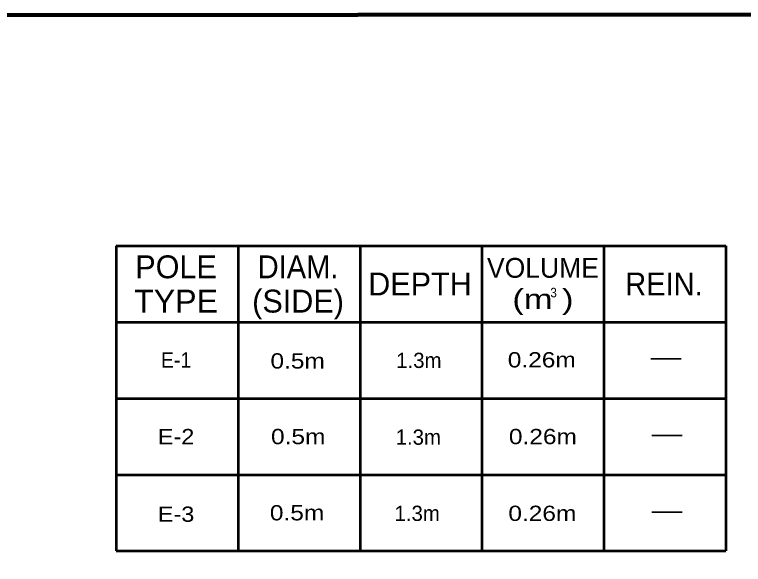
# Model space of a CAD drawing. Extents: x -761 to 95, y 34 to 578.
# Drawn here: x -361.7 to -247, y 485.5 to 571.9 of the extents above; entities that cross this region are included whole.
import ezdxf
from ezdxf.enums import TextEntityAlignment as Align

# ---------------------------------------------------------------- set-up
doc = ezdxf.new("R2010")
doc.units = 0
doc.header["$LTSCALE"] = 0.96
doc.layers.add('1', color=7, linetype='Continuous', lineweight=53)

msp = doc.modelspace()

# ---------------------------------------------------------------- linework, layer by layer
at = {"layer": '1'}
for p, q in [((-326.5549, 535.5653), (-326.5549, 487.5653)), ((-307.3549, 535.5653), (-307.3549, 487.5653)), ((-288.1549, 535.5653), (-288.1549, 487.5653)), ((-268.9549, 535.5653), (-268.9549, 487.5653)), ((-249.7549, 535.5653), (-249.7549, 487.5653)), ((-345.7549, 523.5653), (-249.7549, 523.5653)), ((-345.7549, 511.5653), (-249.7549, 511.5653)), ((-345.7549, 499.5653), (-249.7549, 499.5653)), ((-345.7549, 487.5653), (-249.7549, 487.5653))]:
    msp.add_line(p, q, dxfattribs=at)
at = {"layer": '1', "lineweight": 35}
for p, q in [((-261.5834, 517.7706), (-256.7834, 517.7706)), ((-261.4345, 505.7119), (-256.6345, 505.7119)), ((-261.4345, 493.6532), (-256.6345, 493.6532))]:
    msp.add_line(p, q, dxfattribs=at)
at = {"layer": '1', "lineweight": 158}
msp.add_lwpolyline([(88.1275, 571.9431), (-703.5725, 571.8431), (-703.4725, 45.8431)], dxfattribs=at)
at = {"layer": '1'}
for points in [[(-345.7549, 535.5653), (-326.5549, 535.5653), (-307.3549, 535.5653), (-288.1549, 535.5653), (-268.9549, 535.5653), (-249.7549, 535.5653)], [(-345.7549, 535.5653), (-345.7549, 523.5653), (-345.7549, 511.5653), (-345.7549, 499.5653), (-345.7549, 487.5653)]]:
    msp.add_lwpolyline(points, dxfattribs=at)

# ---------------------------------------------------------------- texts
for s, height, p in [('POLE', 3.6, (-336.3175, 530.468)), ('VOLUME', 3.12, (-278.5548, 530.5425)), ('DEPTH', 3.6, (-297.9084, 527.768)), ('(SIDE)', 3.6, (-317.113, 525.068)), ('1.3m', 2.4, (-298.0912, 516.3544)), ('1.3m', 2.4, (-298.1799, 504.2776)), ('1.3m', 2.4, (-298.3575, 492.2897))]:
    msp.add_text(s, height=height, dxfattribs=at).set_placement(p, align=Align.CENTER)
for s, height, width, p in [('DIAM.', 3.6, 0.95, (-317.113, 530.468)), ('REIN.', 3.6, 0.95, (-259.4991, 527.768)), ('TYPE', 3.6, 1.05, (-336.3176, 525.068)), ('(m )', 3.12, 1.3, (-278.5549, 525.6226)), ('3', 1.5, 0.9, (-276.8733, 527.4603)), ('E-1', 2.4, 0.95, (-336.3176, 516.4216)), ('0.26m', 2.4, 1.2, (-278.7376, 516.4432)), ('0.5m', 2.4, 1.2, (-317.1784, 516.2656)), ('E-2', 2.4, 1.15, (-336.3176, 504.3629)), ('0.5m', 2.4, 1.2, (-317.0897, 504.3664)), ('0.26m', 2.4, 1.2, (-278.56, 504.3664)), ('0.5m', 2.4, 1.2, (-317.2672, 492.3785)), ('0.26m', 2.4, 1.2, (-278.6488, 492.2897)), ('E-3', 2.4, 1.15, (-336.3176, 492.1554))]:
    msp.add_text(s, height=height, dxfattribs=dict(at, width=width)).set_placement(p, align=Align.CENTER)

doc.saveas('drawing.dxf')
